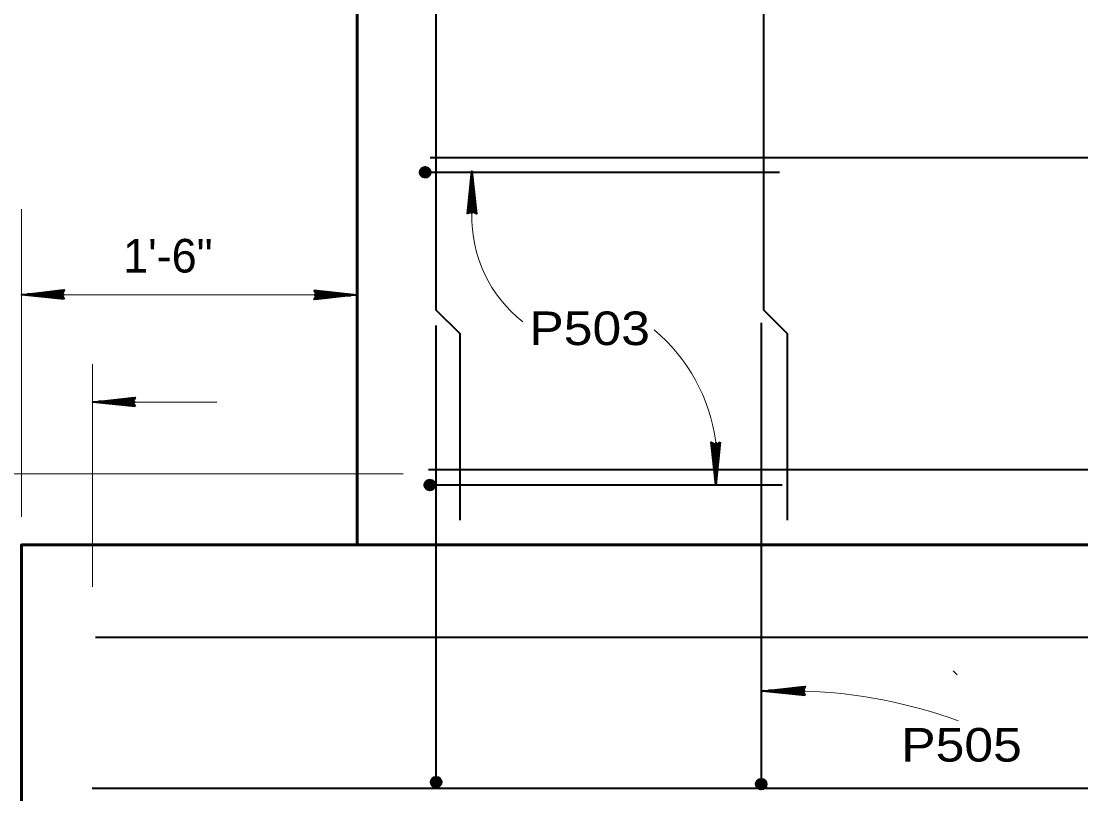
# Model space of a CAD drawing. Extents: x 4.49 to 7.69, y 0.28 to 2.27.
# Drawn here: x 4.7957 to 5.0586, y 0.6207 to 0.8124 of the extents above; entities that cross this region are included whole.
import ezdxf

# ---------------------------------------------------------------- set-up
doc = ezdxf.new("R2010")
doc.units = 0
doc.header["$LTSCALE"] = 0.0033
doc.layers.add('1', color=7, linetype='Continuous', lineweight=35)

msp = doc.modelspace()

# ---------------------------------------------------------------- linework, layer by layer
at = {"layer": '1', "lineweight": 40}
for p, q in [((4.89475, 0.774167), (4.894833, 0.775667)), ((4.894917, 0.774167), (4.895, 0.775667)), ((4.895, 0.774167), (4.895083, 0.775667)), ((4.897, 0.77525), (4.895, 0.775583)), ((4.897, 0.775), (4.895, 0.775417)), ((4.897083, 0.7755), (4.895083, 0.775833)), ((4.897, 0.775417), (4.895083, 0.77575)), ((4.895083, 0.774167), (4.895167, 0.775667)), ((4.897, 0.775333), (4.895083, 0.775667)), ((4.895167, 0.774167), (4.89525, 0.775667)), ((4.89525, 0.774167), (4.895333, 0.775667)), ((4.895333, 0.774167), (4.895417, 0.775667)), ((4.895417, 0.774167), (4.8955, 0.775667)), ((4.895417, 0.774167), (4.8955, 0.775667)), ((4.8955, 0.774167), (4.895667, 0.775667)), ((4.895667, 0.774167), (4.895833, 0.775667)), ((4.895833, 0.774083), (4.895917, 0.775583)), ((4.895917, 0.774083), (4.896, 0.775583)), ((4.896, 0.774083), (4.896083, 0.775583)), ((4.896083, 0.774083), (4.896167, 0.775583)), ((4.896167, 0.774083), (4.89625, 0.775583)), ((4.89625, 0.774083), (4.896333, 0.775583)), ((4.896333, 0.774083), (4.896417, 0.775583)), ((4.8965, 0.774083), (4.896583, 0.775583)), ((4.896583, 0.774083), (4.896667, 0.775583)), ((4.896667, 0.774083), (4.89675, 0.775583)), ((4.89675, 0.774083), (4.896833, 0.775583)), ((4.896833, 0.774083), (4.896917, 0.775583)), ((4.896833, 0.774333), (4.894833, 0.77475)), ((4.896833, 0.77425), (4.894833, 0.774667)), ((4.896833, 0.774167), (4.894833, 0.7745)), ((4.896833, 0.774083), (4.894833, 0.774417)), ((4.89675, 0.773917), (4.894833, 0.77425)), ((4.896917, 0.774667), (4.894917, 0.775083)), ((4.896917, 0.774583), (4.894917, 0.774917)), ((4.896833, 0.7745), (4.894917, 0.774833)), ((4.896917, 0.774833), (4.895, 0.77525)), ((4.896917, 0.77475), (4.895, 0.775167)), ((4.897333, 0.774917), (4.983833, 0.774917)), ((4.898583, 0.736833), (4.898583, 0.625)), ((4.97925, 0.7375), (4.97925, 0.6245)), ((4.895917, 0.696583), (4.896, 0.698083)), ((4.898, 0.69675), (4.896, 0.697167)), ((4.898, 0.696667), (4.896, 0.697083)), ((4.898, 0.696583), (4.896, 0.696917)), ((4.898, 0.6965), (4.896, 0.696833)), ((4.897917, 0.696333), (4.896, 0.696667)), ((4.896083, 0.696583), (4.896167, 0.698083)), ((4.898083, 0.697083), (4.896083, 0.6975)), ((4.898083, 0.697), (4.896083, 0.697333)), ((4.898, 0.696917), (4.896083, 0.69725)), ((4.896167, 0.696583), (4.89625, 0.698083)), ((4.898167, 0.697667), (4.896167, 0.698)), ((4.898167, 0.697417), (4.896167, 0.697833)), ((4.898083, 0.69725), (4.896167, 0.697667)), ((4.898083, 0.697167), (4.896167, 0.697583)), ((4.89825, 0.697917), (4.89625, 0.69825)), ((4.898167, 0.697833), (4.89625, 0.698167)), ((4.89625, 0.696583), (4.896333, 0.698083)), ((4.898167, 0.69775), (4.89625, 0.698083)), ((4.896333, 0.696583), (4.896417, 0.698083)), ((4.896417, 0.696583), (4.8965, 0.698083)), ((4.8965, 0.696583), (4.896583, 0.698083)), ((4.896583, 0.696583), (4.896667, 0.698083)), ((4.896583, 0.696583), (4.896667, 0.698083)), ((4.896667, 0.696583), (4.896833, 0.698083)), ((4.896833, 0.696583), (4.897, 0.698083)), ((4.897, 0.6965), (4.897083, 0.698)), ((4.897083, 0.6965), (4.897167, 0.698)), ((4.897167, 0.6965), (4.89725, 0.698)), ((4.89725, 0.6965), (4.897333, 0.698)), ((4.897333, 0.6965), (4.897417, 0.698)), ((4.897417, 0.6965), (4.8975, 0.698)), ((4.8975, 0.6965), (4.897583, 0.698)), ((4.897667, 0.6965), (4.89775, 0.698)), ((4.89775, 0.6965), (4.897833, 0.698)), ((4.897833, 0.6965), (4.897917, 0.698)), ((4.897917, 0.6965), (4.898, 0.698)), ((4.898, 0.6965), (4.898083, 0.698)), ((4.8985, 0.697333), (4.9845, 0.697333)), ((4.898, 0.62475), (4.897667, 0.62275)), ((4.898083, 0.624667), (4.89775, 0.62275)), ((4.898167, 0.624667), (4.897833, 0.62275)), ((4.899333, 0.623333), (4.897833, 0.6235)), ((4.899333, 0.623167), (4.897833, 0.623333)), ((4.899333, 0.623083), (4.897833, 0.623167)), ((4.899333, 0.623083), (4.897833, 0.623167)), ((4.899333, 0.623), (4.897833, 0.623083)), ((4.899333, 0.622917), (4.897833, 0.623)), ((4.89825, 0.624667), (4.897917, 0.622667)), ((4.899417, 0.6245), (4.897917, 0.624583)), ((4.899417, 0.624417), (4.897917, 0.6245)), ((4.899417, 0.624333), (4.897917, 0.624417)), ((4.899417, 0.62425), (4.897917, 0.624333)), ((4.899417, 0.624167), (4.897917, 0.62425)), ((4.899417, 0.624), (4.897917, 0.624083)), ((4.899417, 0.623917), (4.897917, 0.624)), ((4.899417, 0.623833), (4.897917, 0.623917)), ((4.899417, 0.62375), (4.897917, 0.623833)), ((4.899417, 0.623667), (4.897917, 0.62375)), ((4.899417, 0.623583), (4.897917, 0.623667)), ((4.899417, 0.6235), (4.897917, 0.623583)), ((4.8985, 0.624667), (4.898083, 0.622667)), ((4.898667, 0.624583), (4.89825, 0.622667)), ((4.89875, 0.624583), (4.898333, 0.622667)), ((4.898833, 0.624583), (4.898417, 0.622583)), ((4.898917, 0.624583), (4.898583, 0.622583)), ((4.899, 0.6245), (4.898667, 0.622583)), ((4.899167, 0.6245), (4.89875, 0.6225)), ((4.89925, 0.6245), (4.898833, 0.6225)), ((4.899333, 0.6245), (4.899, 0.6225)), ((4.899417, 0.6245), (4.899083, 0.6225)), ((4.899583, 0.624417), (4.89925, 0.6225)), ((4.978667, 0.62425), (4.978333, 0.62225)), ((4.97875, 0.624167), (4.978417, 0.62225)), ((4.978833, 0.624167), (4.9785, 0.62225)), ((4.98, 0.622833), (4.9785, 0.623)), ((4.978917, 0.624167), (4.978583, 0.622167)), ((4.980083, 0.624), (4.978583, 0.624083)), ((4.980083, 0.623917), (4.978583, 0.624)), ((4.980083, 0.623833), (4.978583, 0.623917)), ((4.980083, 0.62375), (4.978583, 0.623833)), ((4.980083, 0.623667), (4.978583, 0.62375)), ((4.980083, 0.6235), (4.978583, 0.623583)), ((4.980083, 0.623417), (4.978583, 0.6235)), ((4.980083, 0.623333), (4.978583, 0.623417)), ((4.980083, 0.62325), (4.978583, 0.623333)), ((4.980083, 0.623167), (4.978583, 0.62325)), ((4.980083, 0.623083), (4.978583, 0.623167)), ((4.980083, 0.623), (4.978583, 0.623083)), ((4.979167, 0.624167), (4.97875, 0.622167)), ((4.979333, 0.624083), (4.978917, 0.622167)), ((4.979417, 0.624083), (4.979, 0.622167)), ((4.9795, 0.624083), (4.979083, 0.622083)), ((4.979583, 0.624083), (4.97925, 0.622083)), ((4.979667, 0.624), (4.979333, 0.622083)), ((4.979833, 0.624), (4.979417, 0.622)), ((4.979917, 0.624), (4.9795, 0.622)), ((4.98, 0.624), (4.979667, 0.622)), ((4.980083, 0.624), (4.97975, 0.622)), ((4.98025, 0.623917), (4.979917, 0.622)), ((4.899333, 0.622833), (4.897833, 0.622917)), ((4.899333, 0.62275), (4.897833, 0.622833)), ((4.899333, 0.622667), (4.897833, 0.62275)), ((4.899333, 0.622583), (4.897833, 0.622667)), ((4.899333, 0.622417), (4.897833, 0.6225)), ((4.98, 0.622667), (4.9785, 0.622833)), ((4.98, 0.622583), (4.9785, 0.622667)), ((4.98, 0.622583), (4.9785, 0.622667)), ((4.98, 0.6225), (4.9785, 0.622583)), ((4.98, 0.622417), (4.9785, 0.6225)), ((4.98, 0.622333), (4.9785, 0.622417)), ((4.98, 0.62225), (4.9785, 0.622333)), ((4.98, 0.622167), (4.9785, 0.62225)), ((4.98, 0.622083), (4.9785, 0.622167)), ((4.98, 0.621917), (4.9785, 0.622))]:
    msp.add_line(p, q, dxfattribs=at)
at = {"layer": '1'}
for p, q in [((4.9075, 0.764583), (4.9075, 0.775167)), ((4.9065, 0.764833), (4.907417, 0.772667)), ((4.9065, 0.764833), (4.907417, 0.772667)), ((4.906583, 0.764833), (4.907417, 0.772667)), ((4.906667, 0.764833), (4.9075, 0.772667)), ((4.906667, 0.764833), (4.907667, 0.772667)), ((4.908167, 0.76475), (4.907417, 0.772083)), ((4.908333, 0.764833), (4.9075, 0.772167)), ((4.908417, 0.764833), (4.907667, 0.772167)), ((4.908583, 0.764833), (4.90775, 0.772167)), ((4.806333, 0.7445), (4.79575, 0.7445)), ((4.806083, 0.743667), (4.79825, 0.744667)), ((4.806083, 0.743667), (4.79825, 0.7445)), ((4.806083, 0.7435), (4.79825, 0.744417)), ((4.806083, 0.7435), (4.79825, 0.744417)), ((4.806083, 0.743583), (4.79825, 0.744417)), ((4.806083, 0.745583), (4.79875, 0.74475)), ((4.806083, 0.745417), (4.79875, 0.744667)), ((4.806083, 0.745333), (4.79875, 0.7445)), ((4.806167, 0.745167), (4.798833, 0.744417)), ((4.868417, 0.7445), (4.879, 0.7445)), ((4.868583, 0.743833), (4.875917, 0.744583)), ((4.868667, 0.7455), (4.8765, 0.744583)), ((4.868667, 0.7455), (4.8765, 0.744583)), ((4.868667, 0.745417), (4.8765, 0.744583)), ((4.868667, 0.745333), (4.8765, 0.7445)), ((4.868667, 0.745333), (4.8765, 0.744333)), ((4.868667, 0.743667), (4.876, 0.7445)), ((4.868667, 0.743583), (4.876, 0.744333)), ((4.868667, 0.743417), (4.876, 0.74425)), ((4.824, 0.717833), (4.813417, 0.717833)), ((4.82375, 0.717), (4.815917, 0.718)), ((4.82375, 0.717), (4.815917, 0.717833)), ((4.82375, 0.716833), (4.815917, 0.71775)), ((4.82375, 0.716833), (4.815917, 0.71775)), ((4.82375, 0.716917), (4.815917, 0.71775)), ((4.82375, 0.718917), (4.816417, 0.718083)), ((4.82375, 0.71875), (4.816417, 0.718)), ((4.82375, 0.718667), (4.816417, 0.717833)), ((4.823833, 0.7185), (4.8165, 0.71775)), ((4.966917, 0.707667), (4.96775, 0.700333)), ((4.967083, 0.707667), (4.967833, 0.700333)), ((4.967167, 0.707667), (4.968, 0.700333)), ((4.967333, 0.70775), (4.968083, 0.700417)), ((4.968833, 0.707667), (4.967833, 0.699833)), ((4.968, 0.707917), (4.968, 0.697333)), ((4.968833, 0.707667), (4.968, 0.699833)), ((4.969, 0.707667), (4.968083, 0.699833)), ((4.969, 0.707667), (4.968083, 0.699833)), ((4.968917, 0.707667), (4.968083, 0.699833)), ((4.989917, 0.64725), (4.982583, 0.646417)), ((4.989917, 0.647083), (4.982583, 0.646333)), ((4.989917, 0.647), (4.982583, 0.646167)), ((4.99, 0.646833), (4.982667, 0.646083)), ((4.990167, 0.646167), (4.979583, 0.646167)), ((4.989917, 0.645333), (4.982083, 0.646333)), ((4.989917, 0.645333), (4.982083, 0.646167)), ((4.989917, 0.645167), (4.982083, 0.646083)), ((4.989917, 0.645167), (4.982083, 0.646083)), ((4.989917, 0.64525), (4.982083, 0.646083))]:
    msp.add_line(p, q, dxfattribs=at)
at = {"layer": '1', "lineweight": 13}
for p, q in [((4.79575, 0.689417), (4.79575, 0.76575)), ((4.795667, 0.7445), (4.878583, 0.7445)), ((4.813417, 0.672), (4.813417, 0.72725)), ((4.823417, 0.717833), (4.84425, 0.717833)), ((4.8905, 0.700083), (4.714917, 0.700083)), ((4.898583, 0.625), (4.898583, 0.624917)), ((4.97925, 0.6245), (4.97925, 0.62275))]:
    msp.add_line(p, q, dxfattribs=at)
at = {"layer": '1', "lineweight": 25}
msp.add_line((5.026917, 0.651167), (5.027917, 0.650167), dxfattribs=at)
at = {"layer": '1', "lineweight": 60}
for points in [[(4.79575, 0.599083), (4.79575, 0.682417), (4.879083, 0.682417), (4.879083, 1.01575)], [(4.879083, 0.682417), (5.12225, 0.682417), (5.462417, 0.682417)]]:
    msp.add_lwpolyline(points, dxfattribs=at)
at = {"layer": '1', "lineweight": 40}
for points in [[(4.9045, 0.998333), (4.9045, 0.955), (4.898583, 0.949083), (4.898583, 0.74075), (4.9045, 0.734833), (4.9045, 0.688583)], [(4.98575, 0.998333), (4.98575, 0.955), (4.979833, 0.949083), (4.979833, 0.74075), (4.98575, 0.734833), (4.98575, 0.688583)], [(4.897167, 0.7785), (5.122333, 0.7785), (5.448083, 0.7785)], [(4.89725, 0.774917), (4.894667, 0.774583), (4.897, 0.774083), (4.894667, 0.775167), (4.897083, 0.775583), (4.895083, 0.775917), (4.895083, 0.773833), (4.896, 0.776167), (4.89575, 0.773583), (4.89675, 0.775917), (4.896417, 0.773583), (4.895583, 0.776167), (4.897167, 0.774417), (4.89475, 0.77425), (4.896417, 0.776083), (4.895333, 0.773667), (4.897, 0.774083), (4.897083, 0.775583), (4.896, 0.776167), (4.895083, 0.775917), (4.894667, 0.775167), (4.89475, 0.77425), (4.895333, 0.773667), (4.896, 0.77475), (4.894833, 0.775667), (4.89675, 0.775917), (4.896, 0.77475), (4.897083, 0.77425), (4.896083, 0.773583), (4.896, 0.774667), (4.895167, 0.775917), (4.897167, 0.774667), (4.895833, 0.774333), (4.895083, 0.773833)], [(4.89675, 0.701167), (5.122333, 0.701167), (5.447667, 0.701167)], [(4.898417, 0.697333), (4.895833, 0.697), (4.898167, 0.6965), (4.895833, 0.697583), (4.89825, 0.698), (4.89625, 0.698333), (4.89625, 0.69625), (4.897167, 0.698583), (4.896917, 0.696), (4.897917, 0.698333), (4.897583, 0.696), (4.89675, 0.698583), (4.898333, 0.696833), (4.895917, 0.696667), (4.897583, 0.6985), (4.8965, 0.696083), (4.898167, 0.6965), (4.89825, 0.698), (4.897167, 0.698583), (4.89625, 0.698333), (4.895833, 0.697583), (4.895917, 0.696667), (4.8965, 0.696083), (4.897167, 0.697167), (4.896, 0.698083), (4.897917, 0.698333), (4.897167, 0.697167), (4.89825, 0.696667), (4.89725, 0.696), (4.897167, 0.697083), (4.896333, 0.698333), (4.898333, 0.697083), (4.897, 0.69675), (4.89625, 0.69625)], [(4.814167, 0.6595), (5.12225, 0.6595), (5.184, 0.6595)], [(4.898583, 0.624917), (4.898917, 0.622333), (4.899417, 0.624667), (4.898333, 0.622333), (4.897917, 0.62475), (4.897583, 0.62275), (4.899667, 0.62275), (4.897333, 0.623667), (4.899917, 0.623417), (4.897583, 0.624417), (4.899917, 0.624083), (4.897333, 0.62325), (4.899083, 0.624833), (4.89925, 0.622417), (4.897417, 0.624083), (4.899833, 0.623), (4.899417, 0.624667), (4.897917, 0.62475), (4.897333, 0.623667), (4.897583, 0.62275), (4.898333, 0.622333), (4.89925, 0.622417), (4.899833, 0.623), (4.89875, 0.623667), (4.897833, 0.6225), (4.897583, 0.624417), (4.89875, 0.623667), (4.89925, 0.62475), (4.899917, 0.62375), (4.898833, 0.623667), (4.897583, 0.622833), (4.898833, 0.624833), (4.899167, 0.6235), (4.899667, 0.62275)], [(4.97925, 0.624417), (4.979583, 0.621833), (4.980083, 0.624167), (4.979, 0.621833), (4.978583, 0.62425), (4.97825, 0.62225), (4.980333, 0.62225), (4.978, 0.623167), (4.980583, 0.622917), (4.97825, 0.623917), (4.980583, 0.623583), (4.978, 0.62275), (4.97975, 0.624333), (4.979917, 0.621917), (4.978083, 0.623583), (4.9805, 0.6225), (4.980083, 0.624167), (4.978583, 0.62425), (4.978, 0.623167), (4.97825, 0.62225), (4.979, 0.621833), (4.979917, 0.621917), (4.9805, 0.6225), (4.979417, 0.623167), (4.9785, 0.622), (4.97825, 0.623917), (4.979417, 0.623167), (4.979917, 0.62425), (4.980583, 0.62325), (4.9795, 0.623167), (4.97825, 0.622333), (4.9795, 0.624333), (4.979833, 0.623), (4.980333, 0.62225)], [(4.813333, 0.622083), (5.122333, 0.622083), (5.18425, 0.622083)]]:
    msp.add_lwpolyline(points, dxfattribs=at)
at = {"layer": '1'}
for points in [[(4.906417, 0.764583), (4.9075, 0.775167), (4.908667, 0.764583), (4.9075, 0.765167)], [(4.907417, 0.765333), (4.907333, 0.77), (4.907417, 0.77), (4.907417, 0.769083), (4.907333, 0.765333), (4.90725, 0.768333), (4.907167, 0.765167), (4.907083, 0.767417), (4.907, 0.765167), (4.90725, 0.768667), (4.907417, 0.773333), (4.907667, 0.772417), (4.907667, 0.773667), (4.907667, 0.765333), (4.907833, 0.76775), (4.907833, 0.765167), (4.907417, 0.7705), (4.908083, 0.765167)], [(4.806333, 0.743417), (4.79575, 0.7445), (4.806333, 0.745667), (4.80575, 0.7445)], [(4.805583, 0.744417), (4.800917, 0.744333), (4.800917, 0.744417), (4.801833, 0.744417), (4.805583, 0.744333), (4.802583, 0.74425), (4.80575, 0.744167), (4.8035, 0.744083), (4.80575, 0.744), (4.80225, 0.74425), (4.797583, 0.744417), (4.7985, 0.744667), (4.79725, 0.744667), (4.805583, 0.744667), (4.803167, 0.744833), (4.80575, 0.744833), (4.800417, 0.744417), (4.80575, 0.745083)], [(4.868417, 0.745583), (4.879, 0.7445), (4.868417, 0.743333), (4.869, 0.7445)], [(4.869167, 0.744583), (4.873833, 0.744667), (4.873833, 0.744583), (4.872917, 0.744583), (4.869167, 0.744667), (4.872167, 0.74475), (4.869, 0.744833), (4.87125, 0.744917), (4.869, 0.745), (4.8725, 0.74475), (4.877167, 0.744583), (4.87625, 0.744333), (4.8775, 0.744333), (4.869167, 0.744333), (4.871583, 0.744167), (4.869, 0.744167), (4.874333, 0.744583), (4.869, 0.743917)], [(4.824, 0.71675), (4.813417, 0.717833), (4.824, 0.719), (4.823417, 0.717833)], [(4.82325, 0.71775), (4.818583, 0.717667), (4.818583, 0.71775), (4.8195, 0.71775), (4.82325, 0.717667), (4.82025, 0.717583), (4.823417, 0.7175), (4.821167, 0.717417), (4.823417, 0.717333), (4.819917, 0.717583), (4.81525, 0.71775), (4.816167, 0.718), (4.814917, 0.718), (4.82325, 0.718), (4.820833, 0.718167), (4.823417, 0.718167), (4.818083, 0.71775), (4.823417, 0.718417)], [(4.969083, 0.707917), (4.968, 0.697333), (4.966833, 0.707917), (4.968, 0.707333)], [(4.968083, 0.707167), (4.968167, 0.7025), (4.968083, 0.7025), (4.968083, 0.703417), (4.968167, 0.707167), (4.96825, 0.704167), (4.968333, 0.707333), (4.968417, 0.705083), (4.9685, 0.707333), (4.96825, 0.703833), (4.968083, 0.699167), (4.967833, 0.700083), (4.967833, 0.698833), (4.967833, 0.707167), (4.967667, 0.70475), (4.967667, 0.707333), (4.968083, 0.702), (4.967417, 0.707333)], [(4.990167, 0.645083), (4.979583, 0.646167), (4.990167, 0.647333), (4.989583, 0.646167)], [(4.989417, 0.646083), (4.98475, 0.646), (4.98475, 0.646083), (4.985667, 0.646083), (4.989417, 0.646), (4.986417, 0.645917), (4.989583, 0.645833), (4.987333, 0.64575), (4.989583, 0.645667), (4.986083, 0.645917), (4.981417, 0.646083), (4.982333, 0.646333), (4.981083, 0.646333), (4.989417, 0.646333), (4.987, 0.6465), (4.989583, 0.6465), (4.98425, 0.646083), (4.989583, 0.64675)]]:
    msp.add_lwpolyline(points, close=True, dxfattribs=at)
for points in [[(4.907417, 0.765333), (4.906667, 0.764917), (4.906917, 0.765167), (4.90725, 0.765333), (4.907167, 0.765583), (4.906833, 0.765417), (4.907583, 0.76525), (4.908083, 0.765083), (4.9085, 0.764833)], [(4.805583, 0.744417), (4.806, 0.743667), (4.80575, 0.743917), (4.805583, 0.74425), (4.805333, 0.744167), (4.8055, 0.743833), (4.805667, 0.744583), (4.805833, 0.745083), (4.806083, 0.7455)], [(4.869167, 0.744583), (4.86875, 0.745333), (4.869, 0.745083), (4.869167, 0.74475), (4.869417, 0.744833), (4.86925, 0.745167), (4.869083, 0.744417), (4.868917, 0.743917), (4.868667, 0.7435)], [(4.82325, 0.71775), (4.823667, 0.717), (4.823417, 0.71725), (4.82325, 0.717583), (4.823, 0.7175), (4.823167, 0.717167), (4.823333, 0.717917), (4.8235, 0.718417), (4.82375, 0.718833)], [(4.968083, 0.707167), (4.968833, 0.707583), (4.968583, 0.707333), (4.96825, 0.707167), (4.968333, 0.706917), (4.968667, 0.707083), (4.967917, 0.70725), (4.967417, 0.707417), (4.967, 0.707667)], [(4.989417, 0.646083), (4.989833, 0.645333), (4.989583, 0.645583), (4.989417, 0.645917), (4.989167, 0.645833), (4.989333, 0.6455), (4.9895, 0.64625), (4.989667, 0.64675), (4.989917, 0.647167)]]:
    msp.add_lwpolyline(points, dxfattribs=at)
at = {"layer": '1', "lineweight": 40}
for centre in [(4.895917, 0.774867), (4.897083, 0.697283), (4.898633, 0.623583), (4.9793, 0.623083)]:
    msp.add_circle(centre, 0.00132, dxfattribs=at)
at = {"layer": '1', "lineweight": 13}
for centre, radius, start, end in [((4.940697, 0.763847), 0.033205, 178.7301, 231.80918), ((4.924613, 0.702239), 0.043757, 7.45528, 49.98176), ((4.985999, 0.523757), 0.12248, 69.86215, 88.05006)]:
    msp.add_arc(centre, radius, start, end, dxfattribs=at)

# ---------------------------------------------------------------- texts
at = {"layer": '1'}
msp.add_text('1\'-6"', height=0.008334, dxfattribs=at).set_placement((4.821, 0.75))
at = {"layer": '1', "width": 1.15}
for s, p in [('P503', (4.92175, 0.732)), ('P505', (5.014, 0.628667))]:
    msp.add_text(s, height=0.008334, dxfattribs=at).set_placement(p)

doc.saveas('drawing.dxf')
